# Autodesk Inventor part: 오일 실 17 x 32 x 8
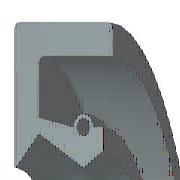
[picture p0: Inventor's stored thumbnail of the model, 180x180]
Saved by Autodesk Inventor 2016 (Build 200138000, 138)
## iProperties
Created: 2012-02
Part Number: 오일 실 17 x 32 x 8
Material: 고무
Description: 샤프트 실 링
Document SubType Name: Modeling
Standard: JIS B 2402
Designer: mdu-01
Standards Organization: JIS
Language: ko-KR
Size Designation: D 17 x 32 x 8
Categories: <MemberInstance><Categories><Category DisplayName="샤프트 부품" InternalName="7f7aeb1f-a693-4053-b835-cee3144e0d98" Mnemonic="SHFT"><Category DisplayName="실링" Intern
Density: 0.93 g/cm^3
Appearance: 고무 - 검은색 - 버전 1.1
IsCustomPart: 1
Author: mdu-01
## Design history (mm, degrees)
revolve "본체" stored, may be unused: angle "d17" = 90 deg
revolve "스프링1" stored, may be unused: angle "d18" = 90 deg
body "Solid1"
sketch "스케치1"
  geometry: L1 (0, 16)-(8, 16); L2 (8, 14.25)-(1.75, 14.25); L3 (1.75, 10.25)-(4.9, 8.5); L4 (4.9, 8.5)-(0, 8.5); L5 (0, 0)-(9.586, 0) reference; L6 (4.9, 8.5)-(6.3, 9.375); L7 (0, 18)-(0, -3) reference; L8 (-1.941, 0)-(11.507, 0) reference; L9 (4.2, 10.6)-(1.75, 11.21); L10 (1.75, 11.21)-(1.75, 14.25); L11 (0, 16)-(0, 8.588); L12 (4.9, 8.5)-(0, 8.5); L13 (1.75, 10.25)-(0.152, 8.528); L14 (8, 16)-(8, 14.25); L15 (5.6, 10.6)-(6.3, 10.6); L16 (6.3, 10.6)-(6.3, 9.375); C1 r 0.455 at (4.9, 10.6); A1 r 0.7 centre (4.9, 10.6) between (5.6, 10.6) and (4.2, 10.6); A2 r 0.088 centre (0.088, 8.588) between (0, 8.588) and (0.152, 8.528); 1 further point
  constraints: 28 end point, 5 horizontal alignment, 5 point on line, 4 point on circle, 4 vertical alignment, 3 centre point, 3 tangent, 2 collinear, 2 horizontal, 2 perpendicular, 1 coincident, 1 parallel
  dimensions: "d0" = 32 diameter of L1 L5 (= SD2); "d1" = 1.75 distance of L1.end L2.start (= SD); "d2" = 0.91 diameter of C1 (= SPDI); "d3" = 1.4 diameter of A1 (= SPDA); "d4" = 17 diameter of L3.end L5 (= NND); "d5" = 20.5 diameter of L3.start L5 (= TKDM); "d7" = 22.42 diameter of L9.end L5 (= TKDM + 0.24 x SWDT); "d8" = 1.75 distance between parallel lines of L11 L10 (= SD); "d9" = 4.9 distance from line of L11 C1.centre (= SPDST); "d10" = 21.2 diameter of C1.centre L5 (= HLDM); "d11" = 0.0875 radius of A2 (= 0.25 x LAB); "d12" = 6.3 distance between parallel lines of L11 L16 (= SDI); "d13" = 18.75 diameter of L6.end L5 (= ABDM); "d14" = 8 distance from line of L11 L1.end (= SWDT)
fillet "모깎기1" dims "d6" = 0.3 (= RR)
other parameters: "SD2" = 32 [user parameter; used in 1 equation term], "SWDT" = 8 [user parameter; used in 2 equation terms], "RR" = 0.3 [user parameter; used in 1 equation term], "SD" = 1.75 [user parameter; used in 2 equation terms], "NND" = 17 [user parameter; used in 1 equation term], "SPDA" = 1.4 [user parameter; used in 1 equation term], "SPDI" = 0.91 [user parameter; used in 1 equation term], "TKDM" = 20.5 [user parameter; used in 2 equation terms], "HLDM" = 21.2 [user parameter; used in 1 equation term], "ABDM" = 18.75 [user parameter; used in 1 equation term], "SDI" = 6.3 [user parameter; used in 1 equation term], "SPDST" = 4.9 [user parameter; used in 1 equation term], "LAB" = 0.35 [user parameter; used in 1 equation term], "d15" = 0, "d16" = 0, "d19" = 0
